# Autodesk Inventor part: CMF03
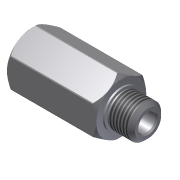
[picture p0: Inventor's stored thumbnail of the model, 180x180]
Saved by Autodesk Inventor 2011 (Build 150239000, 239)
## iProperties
Created: 2015-07
Part Number: CMF03
Document SubType Name: Modeling
Designer: Столбов
Density: 1 g/cm^3
Author: Столбов
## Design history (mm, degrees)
sketch "Эскиз1"
  geometry: L1 (0, 0)-(51, 0); L2 (51, 8.8)-(51, 10.3); L3 (47.981, 16)-(2, 16); L4 (0, 14)-(0, 0); L5 (0, 0)-(80.165, 0); L6 (52, 9.3)-(63, 9.3); L7 (65, 7.3)-(65, 0); L8 (65, 0)-(51, 0); L9 (51, 8.8)-(51, 9.3); L10 (51, 9.3)-(51, 8.8); L11 (51, 0)-(52, 0); L12 (52, 8.8)-(52, 9.3); L13 (51, 8.8)-(52, 8.8); L14 (63, 9.3)-(65, 7.3); L15 (2, 16)-(0, 14); L16 (49.981, 16)-(51, 16); L17 (51, 10.3)-(51, 8.8); L18 (51, 0)-(49.981, 0); L19 (49.981, 10.3)-(49.981, 14); L20 (49.981, 10.3)-(51, 10.3); L21 (49.981, 14)-(47.981, 16); 4 further points
  constraints: 42 end point, 12 point on line, 7 parallel, 5 perpendicular, 3 horizontal
  dimensions: "d0" = 51 distance of point (51, 16) point (0, 16); "d1" = 14 distance of L9.end point (65, 9.3); "d2" = 32 diameter of L3 L5; "d3" = 18.6 diameter of L6 L5; "d4" = 0.5 distance between parallel lines of L6 L13; "d5" = 1 distance between parallel lines of L2 L12; "d6" = 2 distance of L6.end point (65, 9.3); "d7" = 2 distance of L7.start point (65, 9.3) (= d6); "d8" = 2 distance of L3.end point (0, 16) (= d6); "d9" = 2 distance of L4.start point (0, 16) (= d8); "d10" = 1 distance between parallel lines of L20 L6; "d11" = 2 distance of L19.end point (49.981, 16); "d12" = 2 distance of L3.start point (49.981, 16) (= d11)
revolve "Вращение1" sketch "Эскиз1" stored, may be unused: angle "d13" = 90 deg
feature "Резьба1" dims "d14" = 10, "d15" = 0
sketch "Эскиз2"
  geometry: C1 r 14 at (0, 0) reference
hole "Отверстие1" sketch "Эскиз2" at (0, 0) diameter "d16" = 18.631; stored, may be unused: countersink angle "d20" = 90 deg, drill point angle "d22" = 118 deg; dims "d17" = 35, "d18" = 4, "d19" = 2, "d21" = 40
sketch "Эскиз3" dims "d23" = 28
  geometry: L1 (8.083, 14)-(16.166, 0); L2 (16.166, 0)-(8.083, -14); L3 (8.083, -14)-(-8.083, -14); L4 (-8.083, -14)-(-16.166, 0); L5 (-16.166, 0)-(-8.083, 14); L6 (-8.083, 14)-(8.083, 14); C1 r 17.5 at (0, 0); 3 further points
  constraints: 12 end point, 2 coincident, 1 centre point, 1 midpoint, 1 vertical alignment, 15 other
  dimensions: "d24" = 35 diameter of C1
extrude "Выдавливание1" cut sketch "Эскиз3" distance "d25" = 100; taper "d26" = 0 deg
sketch "Эскиз4"
  geometry: 1 further point
hole "Отверстие2" sketch "Эскиз4" at (0, 0) diameter "d27" = 10; stored, may be unused: countersink angle "d31" = 90 deg, drill point angle "d33" = 118 deg; dims "d28" = 6, "d29" = 4, "d30" = 2, "d32" = 50
chamfer "Фаска1" distance "d34" = 1; stored, may be unused: second distance "d35" = 2, angle "d36" = 30 deg
node "Твердое тело1"
